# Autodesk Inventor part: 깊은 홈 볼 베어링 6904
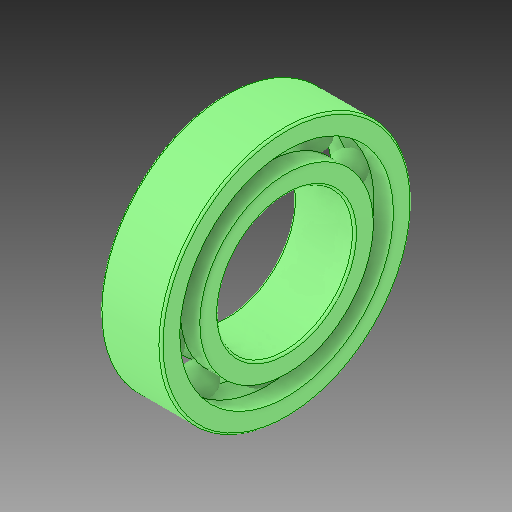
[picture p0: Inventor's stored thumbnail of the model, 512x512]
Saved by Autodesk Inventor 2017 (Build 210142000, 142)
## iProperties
Created: 2024-08
Part Number: 깊은 홈 볼 베어링 6904
Material: 일반
Description: 깊은 그루브 볼 베어링
Document SubType Name: Modeling
Designer: MRC
Density: 1 g/cm^3
Appearance: 기본값
Author: jhkim
Sending System: Autodesk Inventor 2025
Preprocessor: ST-DEVELOPER v20
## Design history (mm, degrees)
feature "Solid1"
feature "Solid1:1"
feature "Solid1:2"
feature "Solid1:3"
feature "Solid1:4"
feature "Solid1:5"
feature "Solid1:6"
feature "Solid1:7"
feature "Solid1:8"
feature "Solid1:9"
feature "Solid1:10"
feature "Solid1:11"
node "솔리드1"
node "솔리드2"
node "솔리드3"
node "솔리드4"
node "솔리드5"
node "솔리드6"
node "솔리드7"
node "솔리드8"
node "솔리드9"
node "솔리드10"
node "솔리드11"
node "솔리드12"
